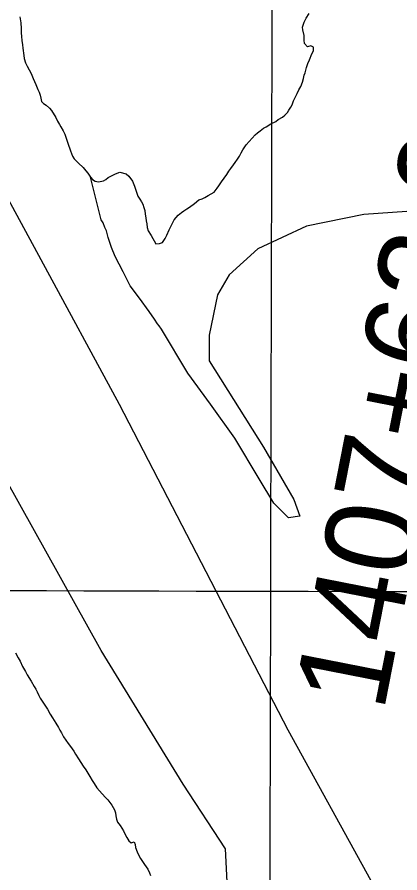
# Model space of a CAD drawing. Extents: x 3187622 to 3225504, y 800805 to 826213.
# Drawn here: x 3196782 to 3197201, y 818051 to 818987 of the extents above; entities that cross this region are included whole.
import ezdxf

# ---------------------------------------------------------------- set-up
doc = ezdxf.new("R2010")
doc.units = 0
for name, color, linetype in [('V-GRID-MAJR', 7, 'Continuous'), ('V-LEVE-TOET', 7, 'Continuous'), ('V-ROAD-CNTR', 7, 'Continuous'), ('V-SITE-VEGE', 7, 'Continuous'), ('V-SURV-IDEN', 7, 'Continuous'), ('V-TOPO-SHOR', 7, 'Continuous')]:
    doc.layers.add(name, color=color, linetype=linetype)

msp = doc.modelspace()

# ---------------------------------------------------------------- linework, layer by layer
at = {"layer": 'V-GRID-MAJR'}
for points in [[(3197031.47, 806236.813), (3197045.574, 812297.071), (3197059.682, 818359.272), (3197073.789, 824421.511), (3197073.793, 824423.414)], [(3191823.839, 818371.837), (3197059.682, 818359.272), (3202295.526, 818347.468), (3207531.372, 818336.426), (3212767.22, 818326.145), (3218003.0700000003, 818316.626), (3223238.92, 818307.868), (3223238.921, 818307.868)]]:
    msp.add_spline(points, degree=3, dxfattribs=at)
at = {"layer": 'V-LEVE-TOET'}
msp.add_lwpolyline([(3197011.838, 818041.454), (3197010.273, 818077.5970000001), (3196963.6750000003, 818148.251), (3196874.1, 818294.476), (3196739.909, 818533.8520000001), (3196601.49, 818781.2490000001), (3196435.525, 819074.072), (3196262.747, 819363.899), (3196287.092, 819398.819), (3196304.068, 819412.172), (3196327.603, 819429.252), (3196345.845, 819437.9770000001), (3196363.623, 819443.762), (3196384.415, 819441.272), (3196400.917, 819427.014), (3196441.284, 819369.496), (3196462.0810000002, 819340.375), (3196495.463, 819297.937), (3196530.29, 819232.059), (3196721.974, 818880.356), (3196893.539, 818563.888), (3197078.431, 818207.479), (3197169.403, 818042.943)], dxfattribs=at)
at = {"layer": 'V-ROAD-CNTR'}
msp.add_spline([(3197108.0137470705, 817982.20200821), (3197162.33863842, 817991.13199035), (3197229.376504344, 818001.8819688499), (3197259.082444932, 817993.6449853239), (3197361.14324081, 818001.169970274), (3197493.7899755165, 818058.5648554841), (3197592.213778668, 818133.79670502), (3197727.971507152, 818194.3225839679), (3197773.223416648, 818262.200448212), (3197795.8503713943, 818360.0592524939), (3197841.10228089, 818435.2911020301), (3197893.7081756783, 818488.4629956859), (3197938.9610851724, 818518.4419357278), (3197968.940025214, 818533.7149051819), (3198014.192934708, 818525.7959210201), (3198044.737873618, 818495.8159809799), (3198127.323708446, 818420.584131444), (3198203.12155685, 818307.4533577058), (3198233.10149689, 818209.029554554), (3198255.7274516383, 818133.79670502), (3198278.353406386, 818073.2718260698), (3198323.60631588, 818005.3939618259), (3198376.2122106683, 817937.515097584), (3198429.383104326, 817900.18217225), (3198459.363044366, 817854.9292627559), (3198466.7170296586, 817832.303308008), (3198489.3429844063, 817756.5054596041), (3198504.614953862, 817703.899564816), (3198542.513878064, 817628.6677152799), (3198633.018697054, 817530.243912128), (3198783.483396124, 817371.8602288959), (3198859.281244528, 817221.3955298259), (3198934.513094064, 817108.264756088)], degree=3, dxfattribs=at)
at = {"layer": 'V-SITE-VEGE'}
for p, q in [((3197096.24, 818981.5039999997), (3197098.393, 818985.9180000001)), ((3197098.393, 818985.9180000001), (3197101.639, 818991.218)), ((3197094.534, 818976.2179999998), (3197096.24, 818981.5039999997)), ((3197094.782, 818973.1460000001), (3197094.534, 818976.2179999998)), ((3197096.375, 818967.234), (3197094.782, 818973.1460000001)), ((3197096.424, 818961.962), (3197096.375, 818967.234)), ((3197096.678, 818958.4519999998), (3197096.424, 818961.962)), ((3197099.789, 818954.528), (3197096.678, 818958.4519999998)), ((3197103.5130000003, 818955.661), (3197099.789, 818954.528)), ((3197106.6010000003, 818954.153), (3197103.5130000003, 818955.661)), ((3197104.473, 818946.8889999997), (3197106.415, 818950.42)), ((3197106.415, 818950.42), (3197106.6010000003, 818954.153)), ((3197100.18, 818936.307), (3197101.901, 818940.2760000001)), ((3197101.901, 818940.2760000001), (3197104.473, 818946.8889999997)), ((3197097.42, 818926.399), (3197098.9020000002, 818932.121)), ((3197098.9020000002, 818932.121), (3197100.18, 818936.307)), ((3197095.505, 818920.011), (3197096.349, 818923.534)), ((3197096.349, 818923.534), (3197097.42, 818926.399)), ((3197090.352, 818907.447), (3197092.732, 818911.422)), ((3197092.732, 818911.422), (3197094.444, 818916.0480000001)), ((3197094.444, 818916.0480000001), (3197095.505, 818920.011)), ((3197084.536, 818895.5329999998), (3197088.632, 818903.697)), ((3197088.632, 818903.697), (3197090.352, 818907.447)), ((3197083.039, 818891.3449999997), (3197084.536, 818895.5329999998)), ((3197075.023, 818879.8520000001), (3197077.849, 818882.733)), ((3197077.849, 818882.733), (3197079.582, 818885.385)), ((3197079.582, 818885.385), (3197081.5270000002, 818888.697)), ((3197081.5270000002, 818888.697), (3197083.039, 818891.3449999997)), ((3197065.203, 818873.169), (3197067.8200000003, 818875.172)), ((3197067.8200000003, 818875.172), (3197072.627, 818877.851)), ((3197072.627, 818877.851), (3197075.023, 818879.8520000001)), ((3197047.952, 818862.907), (3197051.88, 818865.579)), ((3197051.88, 818865.579), (3197054.721, 818867.144)), ((3197054.721, 818867.144), (3197059.741, 818870.265)), ((3197059.741, 818870.265), (3197065.203, 818873.169)), ((3197032.728, 818847.3910000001), (3197042.7260000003, 818858.465)), ((3197042.7260000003, 818858.465), (3197045.12, 818860.685)), ((3197045.12, 818860.685), (3197047.952, 818862.907)), ((3197029.264, 818842.089), (3197032.728, 818847.3910000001)), ((3197025.596, 818835.246), (3197027.323, 818838.556)), ((3197027.323, 818838.556), (3197029.264, 818842.089)), ((3197018.881, 818825.52), (3197020.833, 818828.175)), ((3197020.833, 818828.175), (3197023.434, 818831.711)), ((3197023.434, 818831.711), (3197025.596, 818835.246)), ((3196889.632, 818815.735), (3196894.4450000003, 818817.756)), ((3196894.4450000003, 818817.756), (3196901.273, 818815.6240000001)), ((3197011.512, 818815.131), (3197013.673, 818818.664)), ((3197013.673, 818818.664), (3197016.065, 818821.541)), ((3197016.065, 818821.541), (3197018.881, 818825.52)), ((3196873.967, 818765.387), (3196862.219, 818811.963)), ((3196862.219, 818811.963), (3196864.437, 818809.566)), ((3196864.437, 818809.566), (3196867.309, 818807.838)), ((3196867.309, 818807.838), (3196871.048, 818806.9940000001)), ((3196871.048, 818806.9940000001), (3196876.531, 818807.926)), ((3196876.531, 818807.926), (3196879.15, 818809.487)), ((3196879.15, 818809.487), (3196881.765, 818811.7069999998)), ((3196881.765, 818811.707), (3196885.478, 818813.72)), ((3196885.478, 818813.7199999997), (3196889.632, 818815.735)), ((3196901.273, 818815.6240000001), (3196904.3710000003, 818813.019)), ((3196904.3710000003, 818813.019), (3196908.156, 818807.564)), ((3197005.659, 818807.1680000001), (3197011.512, 818815.131)), ((3196908.156, 818807.564), (3196910.4, 818802.319)), ((3196910.4, 818802.319), (3196912.661, 818795.529)), ((3196997.643, 818795.675), (3197001.115, 818800.0989999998)), ((3197001.115, 818800.0989999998), (3197002.845, 818802.751)), ((3197002.845, 818802.751), (3197005.659, 818807.1680000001)), ((3196912.661, 818795.529), (3196914.017, 818791.3740000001)), ((3196914.017, 818791.3740000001), (3196916.465, 818788.028)), ((3196984.536, 818788.5229999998), (3196987.377, 818789.8690000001)), ((3196987.377, 818789.8690000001), (3196991.09, 818792.099)), ((3196991.09, 818792.099), (3196997.643, 818795.675)), ((3196916.465, 818788.028), (3196918.1750000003, 818785.261)), ((3196918.1750000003, 818785.261), (3196919.444, 818782.492)), ((3196919.444, 818782.492), (3196920.724, 818778.916)), ((3196970.5670000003, 818779.387), (3196976.24, 818783.395)), ((3196976.24, 818783.395), (3196981.034, 818787.174)), ((3196981.034, 818787.174), (3196984.536, 818788.5229999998)), ((3196920.724, 818778.916), (3196921.634, 818775.559)), ((3196921.634, 818775.559), (3196922.33, 818771.539)), ((3196922.33, 818771.539), (3196922.879, 818767.738)), ((3196954.009, 818765.616), (3196958.131, 818770.7059999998)), ((3196958.131, 818770.7059999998), (3196961.838, 818773.595)), ((3196961.838, 818773.595), (3196964.677, 818775.3790000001)), ((3196964.677, 818775.3790000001), (3196967.949, 818777.607)), ((3196967.949, 818777.607), (3196970.5670000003, 818779.387)), ((3197161.6550000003, 818771.259), (3197098.866, 818758.692)), ((3197208.747, 818774.398), (3197161.6550000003, 818771.259)), ((3196876.017, 818762.174), (3196873.967, 818765.387)), ((3196878.0870000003, 818756.937), (3196876.017, 818762.174)), ((3196922.879, 818767.738), (3196923.276, 818764.302)), ((3196923.276, 818764.302), (3196923.893, 818761.086)), ((3196923.893, 818761.086), (3196924.296, 818757.0659999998)), ((3196951.203, 818760.3200000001), (3196954.009, 818765.616)), ((3196879.74, 818753.314), (3196878.0870000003, 818756.937)), ((3196881.829, 818746.058), (3196879.74, 818753.314)), ((3196924.296, 818757.0659999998), (3196925.574, 818753.49)), ((3196925.574, 818753.49), (3196928.697, 818748.468)), ((3196946.044, 818748.632), (3196948.624, 818754.367)), ((3196948.624, 818754.367), (3196951.203, 818760.3200000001)), ((3197098.866, 818758.692), (3197045.495, 818733.561)), ((3196885.165, 818735.175), (3196881.829, 818746.058)), ((3196928.697, 818748.468), (3196933.836, 818739.2929999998)), ((3196941.288, 818740.682), (3196944.1, 818745.1020000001)), ((3196944.1, 818745.1020000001), (3196946.044, 818748.632)), ((3196889.3000000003, 818725.51), (3196885.165, 818735.175)), ((3196933.836, 818739.2929999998), (3196938.003, 818739.5539999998)), ((3196938.003, 818739.554), (3196941.288, 818740.682)), ((3197045.495, 818733.561), (3197014.099, 818705.2880000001)), ((3196897.949, 818708.6140000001), (3196889.3000000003, 818725.51)), ((3196900.005, 818704.996), (3196897.949, 818708.6140000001)), ((3196905.774, 818693.326), (3196900.005, 818704.996)), ((3197014.099, 818705.2880000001), (3197001.541, 818683.299)), ((3196916.0100000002, 818679.6780000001), (3196905.774, 818693.326)), ((3196926.66, 818665.225), (3196916.0100000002, 818679.6780000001)), ((3197001.541, 818683.299), (3196992.122, 818639.3200000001)), ((3196932.396, 818656.79), (3196926.66, 818665.225)), ((3196935.681, 818651.5650000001), (3196932.396, 818656.79)), ((3196937.315, 818649.56), (3196935.681, 818651.5650000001)), ((3196939.9080000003, 818645.88), (3196937.315, 818649.56)), ((3196968.773, 818597.7459999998), (3196939.9080000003, 818645.88)), ((3196992.122, 818639.3200000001), (3196992.122, 818611.05)), ((3196992.122, 818611.05), (3197051.774, 818516.809)), ((3196993.648, 818563.974), (3196968.773, 818597.7459999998)), ((3197020.3000000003, 818526.645), (3196993.648, 818563.974)), ((3197046.955, 818482.208), (3197020.3000000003, 818526.645)), ((3197051.774, 818516.809), (3197084.904, 818459.625)), ((3197062.944, 818455.5430000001), (3197046.955, 818482.208)), ((3197078.934, 818439.544), (3197062.944, 818455.5430000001)), ((3197084.904, 818459.625), (3197091.372, 818441.324)), ((3197091.372, 818441.324), (3197078.934, 818439.5439999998))]:
    msp.add_line(p, q, dxfattribs=at)
at = {"layer": 'V-TOPO-SHOR'}
for points in [[(3196784.801, 818987.345), (3196785.96, 818980.986), (3196786.458, 818974.625), (3196786.503, 818970.013), (3196786.759, 818966.062), (3196787.242, 818961.456), (3196787.723, 818956.848), (3196788.417, 818953.121), (3196789.153, 818945.224), (3196789.622, 818941.935), (3196791.203, 818937.337), (3196792.995, 818933.622), (3196797.242, 818925.537), (3196799.7120000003, 818919.851), (3196801.062, 818916.568), (3196802.629, 818913.289), (3196804.654, 818908.0380000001), (3196806.002, 818904.979), (3196807.13, 818901.694), (3196807.8200000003, 818898.407), (3196808.732, 818894.903), (3196810.95, 818892.728), (3196813.602, 818890.7760000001), (3196817.364, 818887.737), (3196819.586, 818884.902), (3196824.268, 818877.48), (3196826.0640000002, 818873.327), (3196828.294, 818869.6140000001), (3196829.857, 818866.9940000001), (3196832.5330000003, 818862.626), (3196834.1040000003, 818859.128), (3196837.492, 818849.279), (3196840.426, 818840.741), (3196842.6750000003, 818835.054), (3196844.461, 818831.996), (3196846.679, 818829.821), (3196849.116, 818827.429), (3196854.2120000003, 818822.645), (3196857.3200000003, 818819.161), (3196859.54, 818816.5480000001), (3196862.219, 818811.963), (3196864.437, 818809.566), (3196867.309, 818807.838), (3196871.048, 818806.9940000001), (3196876.531, 818807.926), (3196879.15, 818809.487), (3196881.765, 818811.707), (3196885.478, 818813.72), (3196889.632, 818815.735), (3196894.4450000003, 818817.756), (3196901.273, 818815.6240000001), (3196904.3710000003, 818813.019), (3196908.156, 818807.566), (3196910.4, 818802.317), (3196912.661, 818795.529), (3196914.017, 818791.372), (3196916.465, 818788.028), (3196918.1750000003, 818785.261)], [(3196918.1750000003, 818785.261), (3196919.444, 818782.492), (3196920.724, 818778.916), (3196921.634, 818775.559), (3196922.33, 818771.539), (3196922.879, 818767.738), (3196923.276, 818764.302), (3196923.893, 818761.086), (3196924.296, 818757.066), (3196925.574, 818753.49), (3196928.697, 818748.468), (3196933.836, 818739.2930000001), (3196938.003, 818739.554), (3196941.288, 818740.682), (3196944.1, 818745.1020000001), (3196946.044, 818748.632), (3196948.624, 818754.367), (3196951.203, 818760.3200000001), (3196954.009, 818765.616), (3196958.131, 818770.706), (3196961.838, 818773.595), (3196964.677, 818775.3790000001), (3196967.949, 818777.607), (3196970.5670000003, 818779.387), (3196976.24, 818783.395), (3196981.034, 818787.174), (3196984.536, 818788.523), (3196987.377, 818789.8690000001), (3196991.09, 818792.099), (3196997.643, 818795.675), (3197001.115, 818800.099), (3197002.845, 818802.751), (3197005.659, 818807.1680000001), (3197011.512, 818815.131), (3197013.6750000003, 818818.664), (3197016.065, 818821.541), (3197018.881, 818825.52), (3197020.833, 818828.175), (3197023.434, 818831.711), (3197025.596, 818835.246), (3197027.323, 818838.556), (3197029.264, 818842.089), (3197032.728, 818847.3910000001), (3197042.7260000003, 818858.465), (3197045.12, 818860.685), (3197047.952, 818862.907), (3197051.88, 818865.579), (3197054.721, 818867.144), (3197059.741, 818870.265), (3197065.205, 818873.171), (3197067.8200000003, 818875.172), (3197072.627, 818877.853), (3197075.023, 818879.8520000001), (3197077.849, 818882.733), (3197079.582, 818885.385), (3197081.5270000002, 818888.697), (3197083.039, 818891.345), (3197084.536, 818895.533), (3197088.632, 818903.697), (3197090.352, 818907.447), (3197092.732, 818911.422), (3197094.444, 818916.0480000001), (3197095.505, 818920.011), (3197096.349, 818923.534), (3197097.42, 818926.399), (3197098.9020000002, 818932.121), (3197100.18, 818936.307), (3197101.901, 818940.2760000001), (3197104.473, 818946.887), (3197106.417, 818950.42), (3197106.6010000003, 818954.153), (3197103.5130000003, 818955.661), (3197099.789, 818954.528), (3197096.678, 818958.452), (3197096.424, 818961.962), (3197096.375, 818967.234), (3197094.782, 818973.1460000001), (3197094.534, 818976.218), (3197096.24, 818981.5040000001), (3197098.395, 818985.9180000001), (3197101.639, 818991.218)], [(3196780.049, 818291.822), (3196783.177, 818286.286), (3196785.188, 818282.573)], [(3196785.188, 818282.573), (3196788.02, 818277.037), (3196791.002, 818271.43), (3196793.011, 818267.934), (3196797.251, 818260.8740000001), (3196800.599, 818255.05), (3196802.313, 818251.919), (3196803.878, 818249.078), (3196805.889, 818245.1460000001), (3196807.161, 818242.301), (3196811.691, 818235.539), (3196815.181, 818230.3), (3196818.232, 818224.84), (3196820.688, 818220.762), (3196824.548, 818214.944), (3196827.377, 818209.9940000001), (3196828.794, 818207.299), (3196830.506, 818204.167), (3196832.8880000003, 818200.0920000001), (3196837.789, 818192.596), (3196840.31, 818189.328), (3196843.9450000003, 818184.165), (3196845.952, 818180.964), (3196849.292, 818175.87), (3196851.6720000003, 818171.866), (3196854.418, 818167.867), (3196857.165, 818163.867), (3196861.699, 818156.59), (3196864.302, 818152.15), (3196866.383, 818148.876), (3196869.3540000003, 818144.292), (3196872.021, 818140.9500000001), (3196874.98, 818137.612), (3196878.605, 818133.694), (3196881.1180000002, 818130.935), (3196883.561, 818128.103), (3196885.786, 818125.123), (3196888.542, 818120.025), (3196889.671, 818116.89), (3196890.215, 818113.38), (3196890.7600000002, 818109.9450000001), (3196892.036, 818106.59), (3196894.6350000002, 818102.882), (3196896.562, 818100.1190000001), (3196898.495, 818096.9890000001), (3196900.734, 818092.545), (3196902.006, 818089.703), (3196904.16, 818086.135), (3196906.8880000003, 818084.04), (3196910.028, 818085.0210000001), (3196911.373, 818082.105), (3196911.6950000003, 818078.961), (3196913.497, 818074.22), (3196914.771, 818071.011), (3196916.936, 818066.714), (3196919.307, 818063.441), (3196921.607, 818060.316), (3196925.097, 818055.077), (3196926.963, 818051.29), (3196927.944, 818048.225)]]:
    msp.add_lwpolyline(points, dxfattribs=at)

# ---------------------------------------------------------------- texts
at = {"layer": 'V-SURV-IDEN'}
msp.add_text('1407+62.0', height=100.0000000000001, rotation=78.90285785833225, dxfattribs=at).set_placement((3197183.046044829, 818225.8902037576))

doc.saveas('drawing.dxf')
